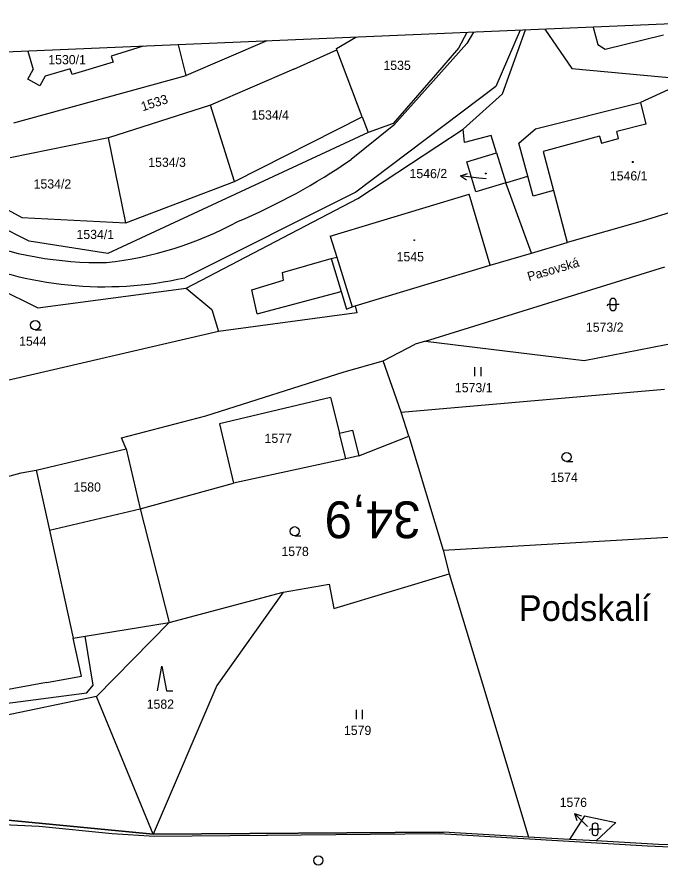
# Model space of a CAD drawing. Extents: x -806456 to -805395, y -1150847 to -1150506.
# Drawn here: x -805749.9 to -805645, y -1150653.3 to -1150515 of the extents above; entities that cross this region are included whole.
import ezdxf

# ---------------------------------------------------------------- set-up
doc = ezdxf.new("R2010")
doc.units = 0
for name, color, linetype in [('Default', 7, 'Continuous'), ('formát', 7, 'Continuous'), ('kilometráž - vrstava 7', 7, 'Continuous'), ('kn_celek - Cisla parcel pomocna', 7, 'Continuous'), ('kn_celek - Cisla pozemkovych parcel', 7, 'Continuous'), ('kn_celek - Cisla stavebnich parcel', 7, 'Continuous'), ('kn_celek - Dalsi prvky mapy popis', 7, 'Continuous'), ('kn_celek - Hranice parcel', 7, 'Continuous'), ('kn_celek - Vnitrni kresby', 7, 'Continuous'), ('kn_celek - Znacky budov', 7, 'Continuous'), ('kn_celek - Znacky kultur', 7, 'Continuous'), ('plochy - SZDC', 7, 'Continuous'), ('PSR_C2_2_trasa_Vimperk - Kabelová trasa', 7, 'Continuous')]:
    doc.layers.add(name, color=color, linetype=linetype)

# ---------------------------------------------------------------- blocks, each defined once
blk = doc.blocks.new('304')
at = {"layer": 'Default'}
blk.add_line((-0.1, 0), (9.9, 0), dxfattribs=at)
blk.add_circle((-0.1, 7.5), 7.5, dxfattribs=at)
blk = doc.blocks.new('306')
at = {"layer": 'Default'}
for p, q in [((-5.2, 0), (-5.2, 15)), ((4.8, 0), (4.8, 15))]:
    blk.add_line(p, q, dxfattribs=at)
blk = doc.blocks.new('316')
at = {"layer": 'Default'}
for p, q in [((-5, 15.5), (-5, 4.5)), ((0.5, 20), (-0.5, 20)), ((5, 4.5), (5, 15.5)), ((-8.3, 10), (-10, 8.1)), ((-5, 10), (-8.3, 10)), ((-5, 10), (5, 10)), ((-0.5, 0), (0.5, 0)), ((10, 10), (5, 10))]:
    blk.add_line(p, q, dxfattribs=at)
for centre, start, end in [((-0.5, 15.5), 90, 180), ((0.5, 15.5), 0, 90), ((-0.5, 4.5), 180, 270), ((0.5, 4.5), 270, 0)]:
    blk.add_arc(centre, 4.5, start, end, dxfattribs=at)
blk = doc.blocks.new('308')
at = {"layer": 'Default'}
for p, q in [((-7.5, 0.2), (0, 40.2)), ((0, 40.2), (7.5, 0.2)), ((7.5, 0.2), (17.5, 0.2))]:
    blk.add_line(p, q, dxfattribs=at)
blk = doc.blocks.new('402')
at = {"layer": 'Default'}
for p, q in [((-0.8, 0.8), (0.7, 0.8)), ((-0.8, 0.8), (-0.8, -0.7)), ((0.7, 0.8), (0.7, -0.7)), ((0.7, -0.7), (-0.8, -0.7))]:
    blk.add_line(p, q, dxfattribs=at)
blk = doc.blocks.new('Z61')
at = {"layer": 'Default'}
for p, q in [((0, 0), (30, 0)), ((30, 0), (19.2, 5.3)), ((30, 0), (19.2, -5.3))]:
    blk.add_line(p, q, dxfattribs=at)

msp = doc.modelspace()

# ---------------------------------------------------------------- linework, layer by layer
at = {"layer": 'formát'}
msp.add_line((-805617.02, -1150514.97), (-805826.83, -1150523.88), dxfattribs=at)
at = {"layer": 'kilometráž - vrstava 7'}
msp.add_circle((-805700.7, -1150652.54), 0.75, dxfattribs=at)
at = {"layer": 'kn_celek - Cisla parcel pomocna'}
msp.add_line((-805673.35, -1150541.38), (-805674.55, -1150541.24), dxfattribs=at)
at = {"layer": 'kn_celek - Hranice parcel'}
for p, q in [((-805676.47, -1150517.49), (-805677.85, -1150520.08)), ((-805670.67, -1150527.5), (-805666.91, -1150517.09)), ((-805663.77, -1150516.95), (-805659.38, -1150523.36)), ((-805709.1, -1150518.88), (-805722.27, -1150524.52)), ((-805697.77, -1150520.14), (-805694.59, -1150518.26)), ((-805722.27, -1150524.52), (-805723.53, -1150519.49)), ((-805704.68, -1150523.49), (-805697.7, -1150520.33)), ((-805697.7, -1150520.33), (-805697.77, -1150520.14)), ((-805693.53, -1150531.26), (-805697.7, -1150520.33)), ((-805677.85, -1150520.08), (-805681.61, -1150524.4)), ((-805704.68, -1150523.49), (-805718.3, -1150529.36)), ((-805659.38, -1150523.36), (-805639.97, -1150525.18)), ((-805750.38, -1150532.24), (-805722.27, -1150524.52)), ((-805681.61, -1150524.4), (-805688.52, -1150532.36)), ((-805677.06, -1150533.28), (-805670.67, -1150527.5)), ((-805718.3, -1150529.36), (-805734.94, -1150534.67)), ((-805714.36, -1150541.82), (-805718.3, -1150529.36)), ((-805714.36, -1150541.82), (-805693.53, -1150531.26)), ((-805693.53, -1150531.26), (-805692.56, -1150533.82)), ((-805688.52, -1150532.36), (-805692.56, -1150533.82)), ((-805692.56, -1150533.82), (-805735.03, -1150553.55)), ((-805694.28, -1150544.59), (-805677.06, -1150533.28)), ((-805676.87, -1150535.44), (-805677.06, -1150533.28)), ((-805672.52, -1150534.3), (-805676.87, -1150535.44)), ((-805671.62, -1150537.13), (-805672.52, -1150534.3)), ((-805734.94, -1150534.67), (-805750.97, -1150537.97)), ((-805732.1, -1150548.55), (-805734.94, -1150534.67)), ((-805676.46, -1150538.59), (-805671.62, -1150537.13)), ((-805671.62, -1150537.13), (-805670.14, -1150542.04)), ((-805747.87, -1150551.52), (-805774.64, -1150538.14)), ((-805766.96, -1150537.88), (-805749.05, -1150547.7)), ((-805674.99, -1150543.49), (-805676.46, -1150538.59)), ((-805732.1, -1150548.55), (-805714.36, -1150541.82)), ((-805670.14, -1150542.04), (-805674.99, -1150543.49)), ((-805665.96, -1150553.47), (-805670.14, -1150542.04)), ((-805634.52, -1150544.15), (-805647.9, -1150548.27)), ((-805722.27, -1150559.18), (-805694.28, -1150544.59)), ((-805749.05, -1150547.7), (-805732.1, -1150548.55)), ((-805647.9, -1150548.27), (-805660.12, -1150551.73)), ((-805735.03, -1150553.55), (-805747.87, -1150551.52)), ((-805665.96, -1150553.47), (-805660.12, -1150551.73)), ((-805672.66, -1150555.46), (-805665.96, -1150553.47)), ((-805763.31, -1150554.09), (-805746.44, -1150562.43)), ((-805694.72, -1150562.1), (-805672.66, -1150555.46)), ((-805683.25, -1150567.84), (-805644.16, -1150555.7)), ((-805746.44, -1150562.43), (-805722.27, -1150559.18)), ((-805722.27, -1150559.18), (-805718.1, -1150562.7)), ((-805694.72, -1150562.1), (-805694.44, -1150563.21)), ((-805718.1, -1150562.7), (-805717.02, -1150566.27)), ((-805694.44, -1150563.21), (-805717.02, -1150566.27)), ((-805717.02, -1150566.27), (-805760.78, -1150576.44)), ((-805683.25, -1150567.84), (-805684.93, -1150568.36)), ((-805683.25, -1150567.84), (-805657.32, -1150571.01)), ((-805657.32, -1150571.01), (-805640.5, -1150567.71)), ((-805690.11, -1150571.04), (-805684.93, -1150568.36)), ((-805696.48, -1150572.83), (-805690.11, -1150571.04)), ((-805687.22, -1150579.45), (-805690.11, -1150571.04)), ((-805719.05, -1150580.01), (-805696.48, -1150572.83)), ((-805687.22, -1150579.45), (-805644.23, -1150575.69)), ((-805732.84, -1150583.59), (-805719.05, -1150580.01)), ((-805685.96, -1150583.32), (-805687.22, -1150579.45)), ((-805732.06, -1150585.41), (-805732.84, -1150583.59)), ((-805694.1, -1150586.53), (-805685.96, -1150583.32)), ((-805685.96, -1150583.32), (-805680.36, -1150601.92)), ((-805746.72, -1150588.87), (-805732.06, -1150585.41)), ((-805732.06, -1150585.41), (-805729.78, -1150595.18)), ((-805696.24, -1150587.04), (-805714.55, -1150591.02)), ((-805694.1, -1150586.53), (-805696.24, -1150587.04)), ((-805752.19, -1150590.12), (-805749.18, -1150589.34)), ((-805749.18, -1150589.34), (-805746.72, -1150588.87)), ((-805746.72, -1150588.87), (-805744.56, -1150598.7)), ((-805729.78, -1150595.18), (-805714.55, -1150591.02)), ((-805729.78, -1150595.18), (-805725.06, -1150613.72)), ((-805744.56, -1150598.7), (-805740.7, -1150616.28)), ((-805680.36, -1150601.92), (-805640.51, -1150599.62)), ((-805680.36, -1150601.92), (-805679.34, -1150605.79)), ((-805698.17, -1150611.46), (-805679.34, -1150605.79)), ((-805679.34, -1150605.79), (-805673.41, -1150625.52)), ((-805706.45, -1150608.8), (-805698.95, -1150607.46)), ((-805698.95, -1150607.46), (-805698.17, -1150611.46)), ((-805725.06, -1150613.72), (-805706.45, -1150608.8)), ((-805706.45, -1150608.8), (-805717.29, -1150624.03)), ((-805738.72, -1150615.96), (-805725.06, -1150613.72)), ((-805725.06, -1150613.72), (-805736.87, -1150625.78)), ((-805740.7, -1150616.28), (-805738.72, -1150615.96)), ((-805737.44, -1150623.94), (-805738.72, -1150615.96)), ((-805738.46, -1150625.19), (-805737.44, -1150623.94)), ((-805717.29, -1150624.03), (-805727.67, -1150648.26)), ((-805736.87, -1150625.78), (-805755.61, -1150629.72)), ((-805755.38, -1150627.4), (-805738.46, -1150625.19)), ((-805727.67, -1150648.26), (-805736.87, -1150625.78)), ((-805673.41, -1150625.52), (-805666.44, -1150648.72)), ((-805787.18, -1150642.48), (-805727.67, -1150648.26)), ((-805657.3, -1150645.28), (-805659.71, -1150649.1)), ((-805657.3, -1150645.28), (-805652.19, -1150646.35)), ((-805652.19, -1150646.35), (-805655.39, -1150649.35)), ((-805727.67, -1150648.26), (-805680.28, -1150647.93)), ((-805666.44, -1150648.72), (-805680.28, -1150647.93)), ((-805659.71, -1150649.1), (-805666.44, -1150648.72)), ((-805655.39, -1150649.35), (-805659.71, -1150649.1)), ((-805645.21, -1150649.93), (-805655.39, -1150649.35)), ((-805611.34, -1150651.29), (-805645.21, -1150649.93))]:
    msp.add_line(p, q, dxfattribs=at)
at = {"layer": 'kn_celek - Vnitrni kresby'}
for p, q in [((-805655.86, -1150516.62), (-805655.12, -1150519.46)), ((-805675.39, -1150517.45), (-805676.5, -1150519.31)), ((-805667.79, -1150517.13), (-805671.74, -1150526.31)), ((-805653.92, -1150520.23), (-805644.38, -1150517.91)), ((-805688.41, -1150532.63), (-805676.5, -1150519.31)), ((-805748.12, -1150520.54), (-805747.25, -1150523.52)), ((-805729.28, -1150519.74), (-805734.5, -1150521.36)), ((-805655.12, -1150519.46), (-805653.92, -1150520.23)), ((-805734.5, -1150521.36), (-805734.16, -1150522.35)), ((-805748.1, -1150525.09), (-805747.25, -1150523.52)), ((-805741.2, -1150523.42), (-805745.28, -1150524.61)), ((-805740.88, -1150524.34), (-805741.2, -1150523.42)), ((-805734.16, -1150522.35), (-805740.88, -1150524.34)), ((-805745.28, -1150524.61), (-805746.13, -1150526.22)), ((-805746.13, -1150526.22), (-805748.1, -1150525.09)), ((-805671.74, -1150526.31), (-805694.59, -1150543.54)), ((-805639.97, -1150525.18), (-805648.16, -1150528.9)), ((-805665.26, -1150533.22), (-805648.16, -1150528.9)), ((-805648.16, -1150528.9), (-805647.26, -1150532.45)), ((-805688.41, -1150532.63), (-805695.35, -1150538.2)), ((-805668, -1150535.58), (-805665.26, -1150533.22)), ((-805647.26, -1150532.45), (-805652.04, -1150533.64)), ((-805654.82, -1150534.42), (-805664.05, -1150536.89)), ((-805654.82, -1150534.42), (-805654.52, -1150535.53)), ((-805651.75, -1150534.8), (-805652.04, -1150533.64)), ((-805666.55, -1150540.95), (-805668, -1150535.58)), ((-805654.52, -1150535.53), (-805651.75, -1150534.8)), ((-805664.05, -1150536.89), (-805662.35, -1150543.3)), ((-805670.14, -1150542.04), (-805666.55, -1150540.95)), ((-805665.67, -1150544.22), (-805666.55, -1150540.95)), ((-805694.59, -1150543.54), (-805722.5, -1150557.5)), ((-805698.8, -1150550.72), (-805676.11, -1150543.89)), ((-805672.66, -1150555.46), (-805676.11, -1150543.89)), ((-805662.35, -1150543.3), (-805665.67, -1150544.22)), ((-805662.35, -1150543.3), (-805660.12, -1150551.73)), ((-805698.8, -1150550.72), (-805697.7, -1150554.12)), ((-805706.54, -1150556.65), (-805698.64, -1150554.39)), ((-805698.64, -1150554.39), (-805697.7, -1150554.12)), ((-805698.64, -1150554.39), (-805696.99, -1150559.76)), ((-805697.7, -1150554.12), (-805695.21, -1150562.25)), ((-805706.39, -1150557.9), (-805706.54, -1150556.65)), ((-805711.53, -1150559.45), (-805706.39, -1150557.9)), ((-805710.66, -1150563.41), (-805711.53, -1150559.45)), ((-805710.66, -1150563.41), (-805696.99, -1150559.76)), ((-805696.99, -1150559.76), (-805696.14, -1150562.64)), ((-805696.14, -1150562.64), (-805695.21, -1150562.25)), ((-805695.21, -1150562.25), (-805694.72, -1150562.1)), ((-805698.71, -1150577.03), (-805716.85, -1150581.35)), ((-805698.71, -1150577.03), (-805697.28, -1150582.87)), ((-805716.85, -1150581.35), (-805714.55, -1150591.02)), ((-805697.28, -1150582.87), (-805695.12, -1150582.35)), ((-805696.24, -1150587.04), (-805697.28, -1150582.87)), ((-805695.12, -1150582.35), (-805694.1, -1150586.53)), ((-805744.56, -1150598.7), (-805729.78, -1150595.18)), ((-805739.33, -1150622.5), (-805740.7, -1150616.28)), ((-805745.04, -1150623.53), (-805739.33, -1150622.5)), ((-805745.04, -1150623.53), (-805754.24, -1150625.19))]:
    msp.add_line(p, q, dxfattribs=at)
for centre, radius, start, end in [((-805754.57, -1150452.06), 104.54, 292.9208, 304.5081), ((-805754.57, -1150452.06), 104.54, 292.9208, 304.5081), ((-805741.73, -1150496.76), 58.63, 276.3363, 298.3839), ((-805741.73, -1150496.76), 58.63, 276.3363, 298.3839), ((-805736.27, -1150495.31), 59.73, 248.7048, 270.9655), ((-805736.27, -1150495.31), 59.73, 248.7048, 270.9655), ((-805735.67, -1150499.41), 59.56, 245.9907, 282.7701), ((-805735.67, -1150499.41), 59.56, 245.9907, 282.7701)]:
    msp.add_arc(centre, radius, start, end, dxfattribs=at)
at = {"layer": 'plochy - SZDC'}
for p, q in [((-805727.67, -1150648.26), (-805787.18, -1150642.48)), ((-805680.28, -1150647.93), (-805727.67, -1150648.26)), ((-805666.44, -1150648.72), (-805680.28, -1150647.93)), ((-805659.71, -1150649.1), (-805666.44, -1150648.72)), ((-805655.39, -1150649.35), (-805659.71, -1150649.1)), ((-805645.21, -1150649.93), (-805655.39, -1150649.35)), ((-805611.34, -1150651.29), (-805645.21, -1150649.93))]:
    msp.add_line(p, q, dxfattribs=at)
at = {"layer": 'PSR_C2_2_trasa_Vimperk - Kabelová trasa'}
for points in [[(-805871.58, -1150644.84), (-805841.67, -1150645.26), (-805829.69, -1150643.07), (-805746.23, -1150646.95), (-805734.34, -1150648.12), (-805727.43, -1150648.58), (-805708.99, -1150648.44)], [(-805709.15, -1150648.44), (-805680.96, -1150648.16), (-805647.01, -1150650.18)], [(-805647.01, -1150650.18), (-805632.04, -1150650.81), (-805624.23, -1150651.13)]]:
    msp.add_lwpolyline(points, dxfattribs=at)

# ---------------------------------------------------------------- block references
at = {"layer": 'kn_celek - Cisla parcel pomocna', "xscale": 0.1}
for p, yscale, rotation in [((-805674.55, -1150541.24), 0.09999999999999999, 173.18808), ((-805656.82, -1150647), 0.10000000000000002, 135)]:
    msp.add_blockref('Z61', p, dxfattribs=dict(at, yscale=yscale, rotation=rotation))
at = {"layer": 'kn_celek - Znacky budov', "xscale": 0.1, "yscale": 0.10000000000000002}
for p in [(-805649.41, -1150538.61), (-805673.4, -1150540.51), (-805685.07, -1150551.38)]:
    msp.add_blockref('402', p, dxfattribs=at)
at = {"layer": 'kn_celek - Znacky kultur', "xscale": 0.1, "yscale": 0.10000000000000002}
for name, p in [('316', (-805652.64, -1150562.87)), ('304', (-805746.88, -1150565.99)), ('306', (-805674.65, -1150573.57)), ('304', (-805660.2, -1150587.49)), ('304', (-805704.55, -1150599.6)), ('308', (-805726.22, -1150624.89)), ('306', (-805693.97, -1150629.48)), ('316', (-805655.55, -1150648.46))]:
    msp.add_blockref(name, p, dxfattribs=at)

# ---------------------------------------------------------------- texts
at = {"layer": 'kilometráž - vrstava 7'}
msp.add_text('34,9', height=6, rotation=180, dxfattribs=at).set_placement((-805684.05, -1150593.98))
at = {"layer": 'kn_celek - Cisla parcel pomocna'}
for s, p in [('1546/2', (-805685.83, -1150541.26)), ('1576', (-805661.34, -1150643.82))]:
    msp.add_text(s, height=1.5, dxfattribs=at).set_placement(p)
at = {"layer": 'kn_celek - Cisla pozemkovych parcel'}
for s, height, p in [('1535', 1.5, (-805690.09, -1150523.61)), ('1534/4', 1.5, (-805711.63, -1150531.71)), ('1534/3', 1.5, (-805728.45, -1150539.42)), ('1534/2', 1.5, (-805747.15, -1150542.95)), ('1534/1', 1.5, (-805740.16, -1150551.19)), ('1573/2', 1.5, (-805657.06, -1150566.31)), ('1544', 1.5, (-805749.52, -1150568.59)), ('1573/1', 1.5, (-805678.43, -1150576.18)), ('1577', 1.5, (-805709.48, -1150584.44)), ('1574', 1.5, (-805662.84, -1150590.81)), ('1580', 1.5, (-805740.64, -1150592.39)), ('1578', 1.5, (-805706.73, -1150602.89)), ('1582', 1.5, (-805728.71, -1150627.8)), ('1579', 1.5, (-805696.53, -1150632.08)), ('1576', 0.1, (-805656.82, -1150646.97))]:
    msp.add_text(s, height=height, dxfattribs=at).set_placement(p)
msp.add_text('1533', height=1.5, rotation=18, dxfattribs=at).set_placement((-805729.35, -1150530.36))
at = {"layer": 'kn_celek - Cisla stavebnich parcel'}
for s, height, p in [('1530/1', 1.5, (-805744.76, -1150522.68)), ('1546/1', 1.5, (-805653.15, -1150541.63)), ('1546/2', 0.1, (-805673.62, -1150541.36)), ('1545', 1.5, (-805687.94, -1150554.83))]:
    msp.add_text(s, height=height, dxfattribs=at).set_placement(p)
at = {"layer": 'kn_celek - Dalsi prvky mapy popis'}
msp.add_text('Pasovská', height=1.5, rotation=16.3634, dxfattribs=at).set_placement((-805666.35, -1150558.08))
msp.add_text('Podskalí', height=4.2, dxfattribs=at).set_placement((-805668.02, -1150613.48))

doc.saveas('drawing.dxf')
